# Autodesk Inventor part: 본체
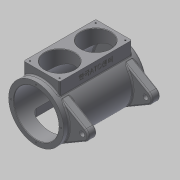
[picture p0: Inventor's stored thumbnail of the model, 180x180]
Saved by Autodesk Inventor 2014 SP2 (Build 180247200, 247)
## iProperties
Created: 2016-11
Part Number: 본체
Material: 일반
Document SubType Name: Modeling
Designer: mduedu
Density: 1 g/cm^3
Appearance: 기본값
Author: mduedu
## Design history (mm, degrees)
sketch "스케치1"
  geometry: C1 r 65 at (0, 0); 1 further point
  constraints: 1 centre point, 1 coincident
  dimensions: "d119" = 130 diameter of C1
extrude "돌출1" new body sketch "스케치1" distance "d3" = 98; taper "d4" = 0 deg; dims "d132" = 97, "d133" = 0
feature "쉘1" dims "d120" = 12, "d134" = 8
node "작업 평면2"
sketch "스케치13"
  geometry: L1 (42.5, 85)-(-42.5, 85); L2 (-42.5, 85)-(-42.5, -85); L3 (-42.5, -85)-(42.5, -85); L4 (42.5, -85)-(42.5, 85); 2 further points
  constraints: 8 end point, 2 parallel, 1 horizontal, 1 midpoint, 1 perpendicular, 1 vertical alignment
  dimensions: "d122" = 170 distance of L1.end L2.end; "d124" = 85 distance of L2.end L3.end; "d125" = 85 distance from line of point (0, 0) L1 (= 0.5 x d122)
extrude "돌출11" join sketch "스케치13" stored distance "d126" = 10; taper "d127" = 0 deg
sketch "스케치14"
  geometry: L1 (65, 97)-(-65, 97) reference; C1 r 35 at (0, 42.5); 1 further point
  constraints: 1 centre point, 1 vertical alignment
  dimensions: "d128" = 70 diameter of C1; "d129" = 54.5 distance from line of C1.centre L1
extrude "돌출12" cut sketch "스케치14" stored distance "d130" = 10; taper "d131" = 0 deg
sketch "스케치15"
  geometry: C1 r 53 at (0, 0) reference; 1 further point
extrude "돌출13" cut sketch "스케치15" stored distance "d135" = 10; taper "d136" = 0 deg
chamfer "모따기1" distance "d54" = 1; stored, may be unused: second distance "d55" = 2, angle "d56" = 45 deg
sketch "스케치8"
  geometry: C1 r 23 at (0, 0); C2 r 65 at (0, 0) reference; 1 further point
  constraints: 1 centre point, 1 concentric
  dimensions: "d57" = 46 diameter of C1
extrude "돌출8" join sketch "스케치8" distance "d58" = 14; taper "d59" = 0 deg
feature "면 기울기1" dims angle "d202" = 10 deg
hole "구멍3" diameter "d62" = 24; stored, may be unused: countersink angle "d66" = 90 deg, drill point angle "d68" = 0 deg; dims "d63" = 6, "d64" = 28, "d65" = 8, "d67" = 14, "d169" = 10, "d170" = 10
fillet "모깎기11" dims "d69" = 3
fillet "모깎기12" dims "d70" = 3
fillet "모깎기13" dims "d71" = 0.3
chamfer "모따기2" distance "d72" = 1; stored, may be unused: second distance "d73" = 2, angle "d74" = 45 deg
node "작업 평면3"
sketch "스케치16"
  geometry: L1 (-42.5, -80)-(52.5, -80); L2 (-42.5, -80)-(24.675, -12.825); L3 (-42.5, -80)-(24.675, -147.175); L4 (3.462, -34.038)-(60.057, -67.042); L5 (3.462, -125.962)-(60.057, -92.958); A1 r 65 centre (-42.5, -80) between (3.462, -34.038) and (3.462, -125.962) reference; A2 r 65 centre (-42.5, -80) between (3.462, -125.962) and (3.462, -34.038); A3 r 95 centre (-42.5, -80) between (52.5, -80) and (24.675, -147.175); A4 r 15 centre (52.5, -80) between (60.057, -67.042) and (60.057, -92.958); 1 further point
  constraints: 10 end point, 9 point on circle, 3 centre point, 3 coincident, 2 point on line, 2 tangent, 1 horizontal
  dimensions: "d140" = 45 deg angle of L3 L1; "d141" = 45 deg angle of L2 L1; "d194" = 30 radial gap between concentric circles of A3 A1; "d195" = 30 diameter of A4
extrude "돌출14" join sketch "스케치16" distance "d143" = 20; taper "d144" = 0 deg
fillet "모깎기25" dims "d196" = 3
fillet "모깎기26" dims "d197" = 3
sketch "스케치22"
  geometry: C1 r 6 at (52.5, -80); A1 r 15 centre (52.5, -80) between (60.057, -92.958) and (60.057, -67.042) reference; 1 further point
  constraints: 1 centre point, 1 coincident
  dimensions: "d198" = 12 diameter of C1
extrude "돌출17" cut sketch "스케치22" stored distance "d200" = 10; taper "d201" = 0 deg
fillet "모깎기20" dims "d159" = 3
fillet "모깎기21" dims "d160" = 3
fillet "모깎기22" dims "d161" = 3
node "작업 평면4"
sketch "스케치18"
  geometry: L1 (-42.5, 65)-(42.5, 65); L2 (42.5, 65)-(42.5, -65); L3 (42.5, -65)-(-42.5, -65); L4 (-42.5, -65)-(-42.5, 65); 2 further points
  constraints: 8 end point, 2 parallel, 1 horizontal, 1 midpoint, 1 perpendicular, 1 vertical alignment
  dimensions: "d162" = 130 distance of L1.end L2.end; "d164" = 85 distance of L2.end L3.end; "d165" = 65 distance from line of point (0, 0) L1 (= 0.5 x d162)
extrude "돌출16" cut sketch "스케치18" stored distance "d166" = 15; taper "d167" = 0 deg
fillet "모깎기23" dims "d168" = 10
fillet "모깎기24" dims "d173" = 3
sketch "스케치19"
  geometry: 4 further points
  constraints: 4 other
hole "구멍6" sketch "스케치19" at (0, -59), (59, 0), (-59, 0), (0, 59) diameter "d174" = 3.242; stored, may be unused: countersink angle "d178" = 90 deg, drill point angle "d180" = 120 deg; dims "d175" = 7, "d176" = 4, "d177" = 2, "d179" = 9
sketch "스케치20"
  geometry: L1 (35, -77.5)-(-35, -77.5); L2 (-35, -77.5)-(-35, -7.5); L3 (-35, -7.5)-(35, -7.5); L4 (35, -7.5)-(35, -77.5); L5 (35, -77.5)-(-35, -7.5); L6 (-35, -77.5)-(35, -7.5); C1 r 36 at (0, -42.5) reference; 3 further points
  constraints: 12 end point, 2 coincident, 2 midpoint, 2 parallel, 1 horizontal, 1 perpendicular
  dimensions: "d181" = 70 distance of L2.end L3.end; "d182" = 70 distance of L1.end L2.end
hole "구멍7" sketch "스케치20" at (-35, -77.5), (35, -77.5) diameter "d183" = 3.242; stored, may be unused: countersink angle "d187" = 90 deg, drill point angle "d189" = 118 deg; dims "d184" = 7, "d185" = 4, "d186" = 2, "d188" = 9
sketch "스케치21"
  geometry: L1 (164, 0)-(0, 0) reference; L2 (-3, 0)-(-3, -24.649) reference; 3 further points
  constraints: 1 midpoint, 1 vertical alignment, 1 other
  dimensions: "d190" = 15 distance from line of point (82, -15) L1; "d191" = 85 distance from line of point (82, 0) L2 (derived)
feature "엠보싱2" sketch "스케치21" dims "d119" = 130, "d192" = 0.5, "d193" = 0
node "솔리드1"
mirror "대칭5"
mirror "대칭6"
mirror "대칭7"
